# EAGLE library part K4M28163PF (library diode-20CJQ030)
SAMSUNG's K4M28163PF - R(B)G/F Mobile-SDRAM 2M x 16Bit x 4 Banks Mobile SDRAM in 54FBGA Organization : 8Mx16 Vdd/Vddq : 1.8V/1.8V Icc1/Icc6 : 40mA/250uA Speed : 133MHz, CL3; 111MHz, CL3; 105MHz, CL3 Please send any comments to: messi@users.sourceforge.net
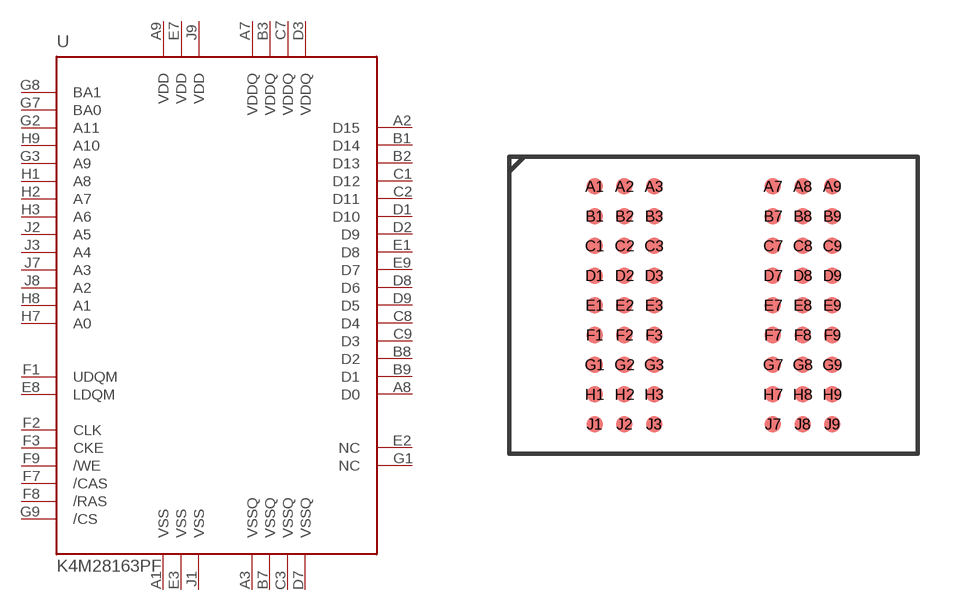
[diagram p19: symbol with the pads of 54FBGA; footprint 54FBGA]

Designator prefix U

## K4M28163PF  [54FBGA]
A1  VSS  pwr
A2  D15
A3  VSSQ  pwr
A7  VDDQ  pwr
A8  D0
A9  VDD  pwr
B1  D14
B2  D13
B3  VDDQ  pwr
B7  VSSQ  pwr
B8  D2
B9  D1
C1  D12
C2  D11
C3  VSSQ  pwr
C7  VDDQ  pwr
C8  D4
C9  D3
D1  D10
D2  D9
D3  VDDQ  pwr
D7  VSSQ  pwr
D8  D6
D9  D5
E1  D8
E2  NC  nc
E3  VSS  pwr
E7  VDD  pwr
E8  LDQM
E9  D7
F1  UDQM
F2  CLK
F3  CKE
F7  /CAS
F8  /RAS
F9  /WE
G1  NC  nc
G2  A11
G3  A9
G7  BA0
G8  BA1
G9  /CS
H1  A8
H2  A7
H3  A6
H7  A0
H8  A1
H9  A10
J1  VSS  pwr
J2  A5
J3  A4
J7  A3
J8  A2
J9  VDD  pwr

## Footprint 54FBGA (pad centres in mm)
54 PIN FBGA Pitch: 0.8mm balldiameter 0.5mm Please send any comments to: messi@users.sourceforge.net
smd 0.45 x 0.45: A1 -3.2,3.2; A2 -2.4,3.2; A3 -1.6,3.2; A7 1.6,3.2; A8 2.4,3.2; A9 3.2,3.2; B1 -3.2,2.4; B2 -2.4,2.4; B3 -1.6,2.4; B7 1.6,2.4; B8 2.4,2.4; B9 3.2,2.4; C1 -3.2,1.6; C2 -2.4,1.6; C3 -1.6,1.6; C7 1.6,1.6; C8 2.4,1.6; C9 3.2,1.6; D1 -3.2,0.8; D2 -2.4,0.8; D3 -1.6,0.8; D7 1.6,0.8; D8 2.4,0.8; D9 3.2,0.8; E1 -3.2,0; E2 -2.4,0; E3 -1.6,0; E7 1.6,0; E8 2.4,0; E9 3.2,0; F1 -3.2,-0.8; F2 -2.4,-0.8; F3 -1.6,-0.8; F7 1.6,-0.8; F8 2.4,-0.8; F9 3.2,-0.8; G1 -3.2,-1.6; G2 -2.4,-1.6; G3 -1.6,-1.6; G7 1.6,-1.6; G8 2.4,-1.6; G9 3.2,-1.6; H1 -3.2,-2.4; H2 -2.4,-2.4; H3 -1.6,-2.4; H7 1.6,-2.4; H8 2.4,-2.4; H9 3.2,-2.4; J1 -3.2,-3.2; J2 -2.4,-3.2; J3 -1.6,-3.2; J7 1.6,-3.2; J8 2.4,-3.2; J9 3.2,-3.2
